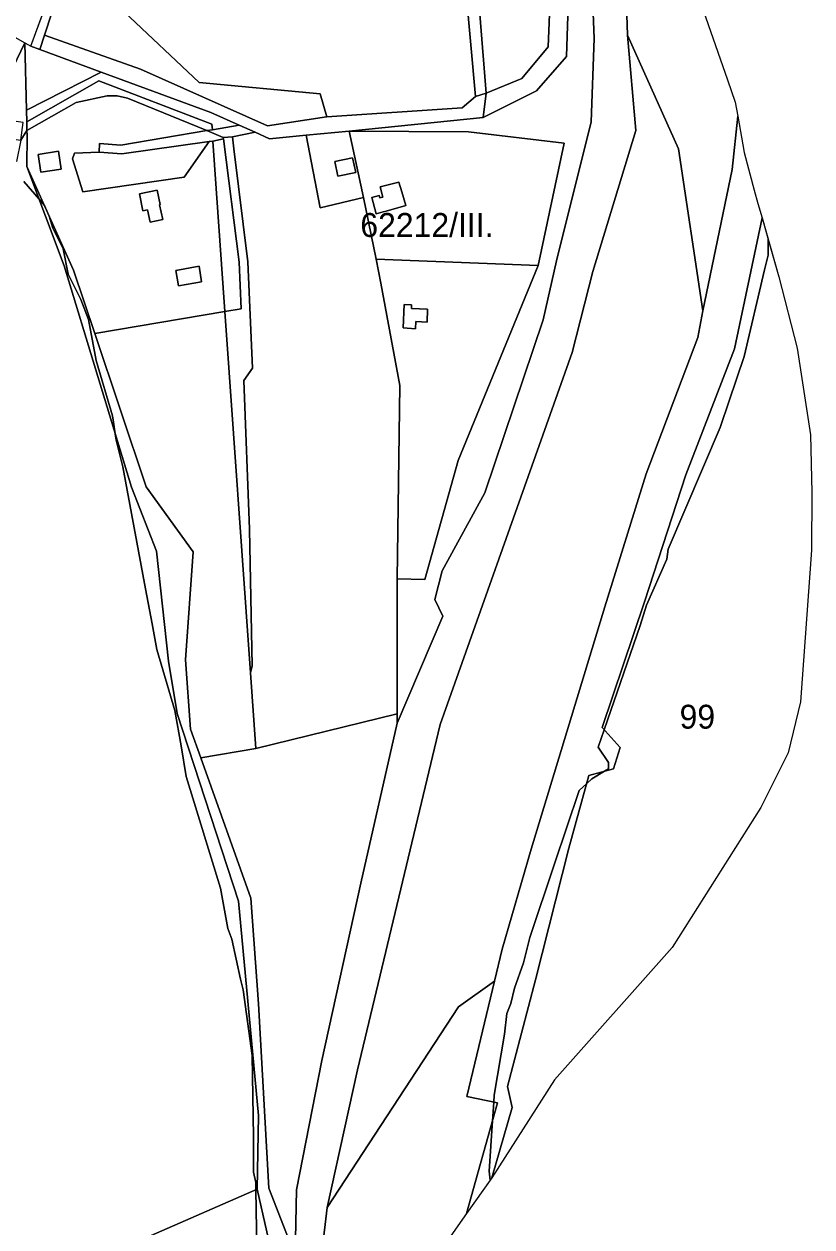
# Model space of a CAD drawing. Extents: x -502026 to -497664, y -1143484 to -1138019.
# Drawn here: x -497965.8 to -497701.9, y -1139162.9 to -1138760.2 of the extents above; entities that cross this region are included whole.
import ezdxf

# ---------------------------------------------------------------- set-up
doc = ezdxf.new("R2010")
doc.units = 0
for name, color, linetype in [('31', 7, 'Continuous'), ('37', 7, 'Continuous'), ('43', 7, 'Continuous'), ('49', 7, 'Continuous'), ('55', 7, 'Continuous'), ('62', 7, 'Continuous'), ('7', 7, 'Continuous')]:
    doc.layers.add(name, color=color, linetype=linetype)

msp = doc.modelspace()

# ---------------------------------------------------------------- linework, layer by layer
at = {"layer": '31'}
for points in [[(-497904.63, -1138795.84), (-497933.37, -1138800.67), (-497940.55, -1138800.12), (-497940.64, -1138803.08), (-497948.95, -1138803.4), (-497949.59, -1138805.23), (-497946.11, -1138816.35), (-497912.25, -1138811.44), (-497903.83, -1138799.49), (-497902.63, -1138799.32), (-497898.57, -1138856.45), (-497942.15, -1138863.79), (-497949.27, -1138842.57), (-497964.89, -1138807.88), (-497964.82, -1138797.41), (-497964.86, -1138795.85), (-497948.36, -1138786.45), (-497938.04, -1138784.16), (-497934.63, -1138784.17), (-497931.2, -1138784.92)], [(-497953.42, -1138808.7), (-497954.26, -1138802.76), (-497961.09, -1138803.81), (-497960.24, -1138809.75)], [(-497920.44, -1138820.65), (-497920.26, -1138820.62), (-497921.28, -1138815.8), (-497927.19, -1138817.02), (-497926, -1138822.72), (-497924.49, -1138822.4), (-497923.63, -1138826.46), (-497919.4, -1138825.58)], [(-497906.43, -1138846.46), (-497907.21, -1138841.25), (-497914.98, -1138842.62), (-497914.06, -1138847.84)], [(-497889.99, -1138977.39), (-497888.19, -1139002.73), (-497906.66, -1139005.8), (-497910.05, -1138996.27), (-497911.76, -1138973.03), (-497909.21, -1138936.84), (-497924.94, -1138915.12), (-497942.15, -1138863.79), (-497898.57, -1138856.45)]]:
    msp.add_lwpolyline(points, close=True, dxfattribs=at)
at = {"layer": '37'}
for points in [[(-497776.14, -1138733.7), (-497774.9, -1138765.04), (-497775.9, -1138792.94), (-497787.44, -1138839.4), (-497791.95, -1138859.17), (-497811.51, -1138917.07), (-497825.74, -1138943.2), (-497828.22, -1138952.85), (-497825.6, -1138958.36), (-497840.85, -1138994.18), (-497840.85, -1138991.11), (-497840.9, -1138945.87), (-497831.57, -1138946.17), (-497820.44, -1138906.33), (-497793.61, -1138841), (-497784.86, -1138800.07), (-497816.91, -1138796.24), (-497856.94, -1138796.02), (-497812.09, -1138791.42), (-497794.18, -1138782.46), (-497784.12, -1138771.02), (-497782.74, -1138730.21), (-497783.56, -1138716.62)], [(-497899.11, -1138798.11), (-497899.05, -1138798.58), (-497902.63, -1138799.32), (-497903.83, -1138799.49), (-497933.05, -1138803.62), (-497940.64, -1138803.08), (-497940.55, -1138800.12), (-497933.37, -1138800.67), (-497904.63, -1138795.84)], [(-497793.61, -1138841), (-497847.91, -1138838.83), (-497852.08, -1138818.25), (-497856.94, -1138796.02), (-497816.91, -1138796.24), (-497784.86, -1138800.07)], [(-497940.64, -1138803.08), (-497933.05, -1138803.62), (-497903.83, -1138799.49), (-497912.25, -1138811.44), (-497946.11, -1138816.35), (-497949.59, -1138805.23), (-497948.95, -1138803.4)], [(-497839.24, -1138816.35), (-497840.24, -1138813.05), (-497846.54, -1138814.65), (-497845.69, -1138818.11), (-497846.7, -1138818.38), (-497846.91, -1138817.55), (-497849.37, -1138818.2), (-497847.88, -1138823.71), (-497845.49, -1138823.04), (-497844.55, -1138822.75), (-497837.93, -1138820.87)], [(-497793.61, -1138841), (-497820.44, -1138906.33), (-497831.57, -1138946.17), (-497840.9, -1138945.87), (-497839.92, -1138881.12), (-497846.28, -1138846.93), (-497847.91, -1138838.83)], [(-497830.66, -1138855.59), (-497836.05, -1138855.35), (-497836, -1138854.17), (-497838.47, -1138854.03), (-497838.84, -1138861.91), (-497834.68, -1138862.18), (-497834.58, -1138859.76), (-497830.85, -1138859.96)]]:
    msp.add_lwpolyline(points, close=True, dxfattribs=at)
at = {"layer": '43'}
for points in [[(-497966.9, -1138799.01), (-497964.86, -1138795.85), (-497964.82, -1138797.41), (-497964.89, -1138807.88), (-497952.46, -1138841.13), (-497929.82, -1138915.26), (-497921.45, -1138936.6), (-497917.4, -1138973.51), (-497914.56, -1138991.04), (-497894.01, -1139053.87), (-497887.27, -1139125.57), (-497887.75, -1139150.31), (-497925.04, -1139166.51)], [(-497925.04, -1139166.51), (-497887.75, -1139150.31), (-497881.28, -1139178.83)]]:
    msp.add_lwpolyline(points, dxfattribs=at)
at = {"layer": '49'}
msp.add_lwpolyline([(-497861.66, -1138428.73), (-497844.68, -1138481.4), (-497801.21, -1138590.61), (-497757.73, -1138699.81), (-497730.19, -1138778.85), (-497727.6, -1138786.3), (-497726.76, -1138791), (-497728.61, -1138808.85), (-497738.41, -1138856.12), (-497746.59, -1138801.9), (-497763.66, -1138763.92), (-497765.25, -1138716.53), (-497775.78, -1138675.36), (-497786.79, -1138640.1), (-497805.05, -1138603.63), (-497850.35, -1138491.93), (-497874.17, -1138447.19), (-497878.23, -1138434.33)], dxfattribs=at)
for points in [[(-497738.41, -1138856.12), (-497740.15, -1138865.09), (-497757.48, -1138910.79), (-497771.29, -1138955.25), (-497795.95, -1139036.37), (-497805.68, -1139069.91), (-497808.25, -1139080.59), (-497820.29, -1139089.21), (-497864.29, -1139156.38), (-497854.17, -1139110.27), (-497826.46, -1138994.7), (-497782.28, -1138870.08), (-497775.26, -1138843.03), (-497760.95, -1138795.84), (-497763.66, -1138763.92), (-497746.59, -1138801.9)], [(-497817.58, -1139158.44), (-497826.73, -1139171.48), (-497838.59, -1139210.88), (-497846.62, -1139303.16), (-497844.4, -1139314.38), (-497843.73, -1139331.53), (-497847.64, -1139390.66), (-497856.69, -1139439.74), (-497870.76, -1139393.48), (-497873.16, -1139231.06), (-497864.29, -1139156.38), (-497820.29, -1139089.21), (-497808.25, -1139080.59), (-497817.54, -1139119.27), (-497807.2, -1139121.34)]]:
    msp.add_lwpolyline(points, close=True, dxfattribs=at)
at = {"layer": '55'}
for points in [[(-497878.23, -1138434.33), (-497874.17, -1138447.19), (-497850.35, -1138491.93), (-497805.05, -1138603.63), (-497786.79, -1138640.1), (-497775.78, -1138675.36), (-497765.25, -1138716.53), (-497763.66, -1138763.92), (-497760.95, -1138795.84), (-497775.26, -1138843.03), (-497782.28, -1138870.08), (-497826.46, -1138994.7), (-497854.17, -1139110.27), (-497864.29, -1139156.38), (-497873.16, -1139231.06)], [(-497875.07, -1139172.63), (-497874.52, -1139150.43), (-497866.12, -1139107.13), (-497853.02, -1139047.85), (-497840.85, -1138994.18), (-497825.6, -1138958.36), (-497828.22, -1138952.85), (-497825.74, -1138943.2), (-497811.51, -1138917.07), (-497791.95, -1138859.17), (-497787.44, -1138839.4), (-497775.9, -1138792.94), (-497774.9, -1138765.04), (-497776.14, -1138733.7)]]:
    msp.add_lwpolyline(points, dxfattribs=at)
for points in [[(-497783.56, -1138716.62), (-497782.74, -1138730.21), (-497784.12, -1138771.02), (-497794.18, -1138782.46), (-497812.09, -1138791.42), (-497811.04, -1138783.26), (-497799.05, -1138778.37), (-497790.3, -1138767.75), (-497788.8, -1138732.41), (-497794.39, -1138691.68)], [(-497959, -1138763.82), (-497960.58, -1138768.67), (-497963.56, -1138767.58), (-497951.59, -1138734.81), (-497950.49, -1138729.96), (-497947.97, -1138728.5), (-497949.52, -1138734.85)], [(-497864.4, -1138791.18), (-497819.07, -1138788.22), (-497814.56, -1138784.41), (-497811.04, -1138783.26), (-497812.09, -1138791.42), (-497856.94, -1138796.02), (-497871.29, -1138797.37), (-497883.62, -1138798.54), (-497888.39, -1138796.38), (-497893.8, -1138793.99), (-497903.25, -1138789.81), (-497940.05, -1138776.24), (-497960.58, -1138768.67), (-497959, -1138763.82), (-497926.84, -1138775.26), (-497884.29, -1138794.23), (-497864.58, -1138791.19)], [(-497965.03, -1138788.96), (-497964.93, -1138792.93), (-497964.86, -1138795.85), (-497966.9, -1138799.01), (-497966.09, -1138793.1), (-497974.72, -1138791.92), (-497975.53, -1138797.83), (-497966.9, -1138799.01), (-497968.32, -1138806.18), (-497978.52, -1138800.78), (-497981.46, -1138799.22), (-497965.6, -1138766.42)], [(-497963.56, -1138767.58), (-497960.58, -1138768.67), (-497940.05, -1138776.24), (-497965.03, -1138788.96), (-497965.6, -1138766.42)], [(-497893.8, -1138793.99), (-497902.72, -1138795.52), (-497902.89, -1138793.64), (-497940.75, -1138779.16), (-497964.93, -1138792.93), (-497965.03, -1138788.96), (-497940.05, -1138776.24), (-497903.25, -1138789.81)], [(-497718.61, -1138825.06), (-497727.86, -1138868.87), (-497744.11, -1138911.12), (-497757.95, -1138953.59), (-497772.19, -1138995.73), (-497766.17, -1139002.36), (-497768.38, -1139009.48), (-497776.61, -1139011.77), (-497783.33, -1139036.08), (-497794.56, -1139080.14), (-497803.89, -1139115.86), (-497802.28, -1139122.88), (-497809.15, -1139146.42), (-497817.58, -1139158.44), (-497807.2, -1139121.34), (-497817.54, -1139119.27), (-497808.25, -1139080.59), (-497805.68, -1139069.91), (-497795.95, -1139036.37), (-497771.29, -1138955.25), (-497757.48, -1138910.79), (-497740.15, -1138865.09), (-497738.41, -1138856.12), (-497728.61, -1138808.85), (-497726.76, -1138791), (-497724.59, -1138803.21), (-497721.27, -1138815.8), (-497719.98, -1138820.29)], [(-497888.39, -1138796.38), (-497896.03, -1138797.95), (-497899.11, -1138798.11), (-497904.63, -1138795.84), (-497902.72, -1138795.52), (-497893.8, -1138793.99)], [(-497852.08, -1138818.25), (-497866.63, -1138821.67), (-497871.29, -1138797.37), (-497856.94, -1138796.02)], [(-497953.42, -1138808.7), (-497960.24, -1138809.75), (-497961.09, -1138803.81), (-497954.26, -1138802.76)], [(-497854.75, -1138809.84), (-497860.68, -1138811.11), (-497861.74, -1138806.18), (-497855.8, -1138804.91)], [(-497854.75, -1138809.84), (-497855.8, -1138804.91), (-497861.74, -1138806.18), (-497860.68, -1138811.11)], [(-497942.15, -1138863.79), (-497924.94, -1138915.12), (-497909.21, -1138936.84), (-497911.76, -1138973.03), (-497910.05, -1138996.27), (-497906.66, -1139005.8), (-497889.89, -1139052.88), (-497887.35, -1139088.19), (-497883.85, -1139149.91), (-497875.07, -1139172.63), (-497881.28, -1139178.83), (-497887.75, -1139150.31), (-497887.27, -1139125.57), (-497894.01, -1139053.87), (-497914.56, -1138991.04), (-497917.4, -1138973.51), (-497921.45, -1138936.6), (-497929.82, -1138915.26), (-497952.46, -1138841.13), (-497964.89, -1138807.88), (-497949.27, -1138842.57)], [(-497839.24, -1138816.35), (-497837.93, -1138820.87), (-497844.55, -1138822.75), (-497845.49, -1138823.04), (-497847.88, -1138823.71), (-497849.37, -1138818.2), (-497846.91, -1138817.55), (-497846.7, -1138818.38), (-497845.69, -1138818.11), (-497846.54, -1138814.65), (-497840.24, -1138813.05)], [(-497920.44, -1138820.65), (-497919.4, -1138825.58), (-497923.63, -1138826.46), (-497924.49, -1138822.4), (-497926, -1138822.72), (-497927.19, -1138817.02), (-497921.28, -1138815.8), (-497920.26, -1138820.62)], [(-497809.15, -1139146.42), (-497802.28, -1139122.88), (-497803.89, -1139115.86), (-497794.56, -1139080.14), (-497783.33, -1139036.08), (-497776.61, -1139011.77), (-497768.38, -1139009.48), (-497766.17, -1139002.36), (-497772.19, -1138995.73), (-497757.95, -1138953.59), (-497744.11, -1138911.12), (-497727.86, -1138868.87), (-497718.61, -1138825.06), (-497712.96, -1138844.74), (-497706.83, -1138868.7), (-497702.34, -1138897.67), (-497701.9, -1138917.01), (-497702.04, -1138936.29), (-497705.79, -1138987.11), (-497709.86, -1139004.22), (-497719.07, -1139022.42), (-497748.69, -1139069.37), (-497788.1, -1139113.61)], [(-497906.43, -1138846.46), (-497914.06, -1138847.84), (-497914.98, -1138842.62), (-497907.21, -1138841.25)], [(-497830.66, -1138855.59), (-497830.85, -1138859.96), (-497834.58, -1138859.76), (-497834.68, -1138862.18), (-497838.84, -1138861.91), (-497838.47, -1138854.03), (-497836, -1138854.17), (-497836.05, -1138855.35)]]:
    msp.add_lwpolyline(points, close=True, dxfattribs=at)
at = {"layer": '62'}
for points in [[(-497757.73, -1138699.81), (-497730.19, -1138778.85), (-497727.6, -1138786.3), (-497726.76, -1138791), (-497724.59, -1138803.21), (-497721.27, -1138815.8), (-497719.98, -1138820.29), (-497718.61, -1138825.06), (-497716.52, -1138832.34), (-497716.53, -1138837.5), (-497717.81, -1138842.5), (-497724.62, -1138871.5), (-497729.66, -1138886.34), (-497732.69, -1138895.25), (-497750.09, -1138936), (-497750.53, -1138939.37), (-497757.31, -1138954.75), (-497759.44, -1138961.5), (-497771.49, -1138996.5), (-497773.47, -1139002.25), (-497770.06, -1139007.37), (-497770.06, -1139009.5), (-497771.41, -1139010.32), (-497775.59, -1139012.87), (-497777.36, -1139014.48), (-497779.84, -1139016.75), (-497788.12, -1139041.37), (-497796.41, -1139066), (-497798.53, -1139074.5), (-497801.5, -1139083), (-497802.78, -1139088.12), (-497804.06, -1139091.5), (-497804.91, -1139098.37), (-497808.31, -1139118.75), (-497808.47, -1139121.09), (-497808.88, -1139127.35), (-497810, -1139144.25), (-497809.75, -1139147.28), (-497817.58, -1139158.44), (-497826.73, -1139171.48)], [(-497968.95, -1138764.58), (-497965.6, -1138766.42), (-497963.56, -1138767.58), (-497959.36, -1138756.08)], [(-497887.75, -1139176.87), (-497888.15, -1139150.48), (-497888.19, -1139148), (-497889.03, -1139144.62), (-497889.03, -1139132.75), (-497889.47, -1139105.5), (-497892.44, -1139083.5), (-497893.28, -1139080), (-497896.25, -1139066.5), (-497897.53, -1139063), (-497900.06, -1139049.5), (-497911.56, -1139012.12), (-497913.25, -1139001.87), (-497915.37, -1138990), (-497921.31, -1138969.62), (-497922.94, -1138960.98), (-497925.16, -1138949.25), (-497932.78, -1138908.37), (-497934.91, -1138899.87), (-497935.07, -1138898.77), (-497935.28, -1138897.37), (-497935.87, -1138893.48), (-497936.19, -1138891.37), (-497941.72, -1138872.75), (-497944.25, -1138859.12), (-497946.81, -1138852.37), (-497951.06, -1138843.87), (-497952.75, -1138835.37), (-497956.16, -1138828.5), (-497957.44, -1138824.43), (-497959.04, -1138820.87), (-497960.79, -1138818.84), (-497965.94, -1138812.87)], [(-497965.94, -1138812.87), (-497960.79, -1138818.84), (-497959.04, -1138820.87), (-497957.44, -1138824.43), (-497956.16, -1138828.5), (-497952.75, -1138835.37), (-497951.06, -1138843.87), (-497946.81, -1138852.37), (-497944.25, -1138859.12), (-497941.72, -1138872.75), (-497936.19, -1138891.37), (-497935.87, -1138893.48), (-497935.28, -1138897.37), (-497935.07, -1138898.77), (-497934.91, -1138899.87), (-497932.78, -1138908.37), (-497925.16, -1138949.25), (-497922.94, -1138960.98), (-497921.31, -1138969.62), (-497915.37, -1138990), (-497913.25, -1139001.87), (-497911.56, -1139012.12), (-497900.06, -1139049.5), (-497897.53, -1139063), (-497896.25, -1139066.5), (-497893.28, -1139080), (-497892.44, -1139083.5), (-497889.47, -1139105.5), (-497889.03, -1139132.75), (-497889.03, -1139144.62), (-497888.19, -1139148), (-497888.15, -1139150.48), (-497887.75, -1139176.87)]]:
    msp.add_lwpolyline(points, dxfattribs=at)
msp.add_lwpolyline([(-497809.75, -1139147.28), (-497810, -1139144.25), (-497808.88, -1139127.35), (-497808.47, -1139121.09), (-497808.31, -1139118.75), (-497804.91, -1139098.37), (-497804.06, -1139091.5), (-497802.78, -1139088.12), (-497801.5, -1139083), (-497798.53, -1139074.5), (-497796.41, -1139066), (-497788.12, -1139041.37), (-497779.84, -1139016.75), (-497777.36, -1139014.48), (-497775.59, -1139012.87), (-497771.41, -1139010.32), (-497770.06, -1139009.5), (-497770.06, -1139007.37), (-497773.47, -1139002.25), (-497771.49, -1138996.5), (-497759.44, -1138961.5), (-497757.31, -1138954.75), (-497750.53, -1138939.37), (-497750.09, -1138936), (-497732.69, -1138895.25), (-497729.66, -1138886.34), (-497724.62, -1138871.5), (-497717.81, -1138842.5), (-497716.53, -1138837.5), (-497716.52, -1138832.34), (-497712.96, -1138844.74), (-497706.83, -1138868.7), (-497702.34, -1138897.67), (-497701.9, -1138917.01), (-497702.04, -1138936.29), (-497705.79, -1138987.11), (-497709.86, -1139004.22), (-497719.07, -1139022.42), (-497748.69, -1139069.37), (-497788.1, -1139113.61), (-497809.15, -1139146.42)], close=True, dxfattribs=at)
at = {"layer": '7'}
for points in [[(-497871.66, -1138500.59), (-497868.16, -1138510.02), (-497836.32, -1138602.52), (-497806.53, -1138663.72), (-497794.39, -1138691.68), (-497788.8, -1138732.41), (-497790.3, -1138767.75), (-497799.05, -1138778.37), (-497811.04, -1138783.26), (-497817.89, -1138698.3), (-497832.77, -1138648.99), (-497844.03, -1138617.45), (-497881.14, -1138505.91), (-497872.21, -1138498.67)], [(-497811.04, -1138783.26), (-497814.56, -1138784.41), (-497822.33, -1138699.07), (-497836.53, -1138652.99), (-497853.3, -1138603.71), (-497884.72, -1138508.82), (-497881.14, -1138505.91), (-497844.03, -1138617.45), (-497832.77, -1138648.99), (-497817.89, -1138698.3)], [(-497902.72, -1138795.52), (-497904.63, -1138795.84), (-497931.2, -1138784.92), (-497934.63, -1138784.17), (-497938.04, -1138784.16), (-497948.36, -1138786.45), (-497964.86, -1138795.85), (-497964.93, -1138792.93), (-497940.75, -1138779.16), (-497902.89, -1138793.64)], [(-497871.29, -1138797.37), (-497866.63, -1138821.67), (-497852.08, -1138818.25), (-497847.91, -1138838.83), (-497846.28, -1138846.93), (-497839.92, -1138881.12), (-497840.9, -1138945.87), (-497840.85, -1138991.11), (-497888.19, -1139002.73), (-497889.99, -1138977.39), (-497889.43, -1138975), (-497890.34, -1138929.36), (-497890.35, -1138929.25), (-497892.24, -1138879.45), (-497889.28, -1138875.35), (-497890.85, -1138839.72), (-497895.55, -1138801.88), (-497896.03, -1138797.95), (-497888.39, -1138796.38), (-497883.62, -1138798.54)], [(-497898.57, -1138856.45), (-497902.63, -1138799.32), (-497899.05, -1138798.58), (-497893.76, -1138839.91), (-497893.16, -1138855.54)], [(-497889.99, -1138977.39), (-497898.57, -1138856.45), (-497893.16, -1138855.54), (-497893.76, -1138839.91), (-497899.05, -1138798.58), (-497899.11, -1138798.11), (-497896.03, -1138797.95), (-497895.55, -1138801.88), (-497890.85, -1138839.72), (-497889.28, -1138875.35), (-497892.24, -1138879.45), (-497890.35, -1138929.25), (-497890.34, -1138929.36), (-497889.43, -1138975)], [(-497840.85, -1138994.18), (-497853.02, -1139047.85), (-497866.12, -1139107.13), (-497874.52, -1139150.43), (-497875.07, -1139172.63), (-497883.85, -1139149.91), (-497887.35, -1139088.19), (-497889.89, -1139052.88), (-497906.66, -1139005.8), (-497888.19, -1139002.73), (-497840.85, -1138991.11)]]:
    msp.add_lwpolyline(points, close=True, dxfattribs=at)
for points in [[(-497822.33, -1138699.07), (-497814.56, -1138784.41), (-497819.07, -1138788.22), (-497864.4, -1138791.18), (-497866.62, -1138783.54), (-497907.13, -1138779.68), (-497932.36, -1138756.1)], [(-497932.36, -1138756.1), (-497907.13, -1138779.68), (-497866.62, -1138783.54), (-497864.4, -1138791.18), (-497864.58, -1138791.19), (-497884.29, -1138794.23), (-497926.84, -1138775.26), (-497959, -1138763.82), (-497949.52, -1138734.85)], [(-497968.95, -1138764.58), (-497965.6, -1138766.42), (-497981.46, -1138799.22)]]:
    msp.add_lwpolyline(points, dxfattribs=at)

# ---------------------------------------------------------------- texts
at = {"layer": '62'}
for s, p in [('62212/III.', (-497853.19, -1138831.43)), ('99', (-497746.24, -1138996.07))]:
    msp.add_text(s, height=8, dxfattribs=at).set_placement(p)

doc.saveas('drawing.dxf')
